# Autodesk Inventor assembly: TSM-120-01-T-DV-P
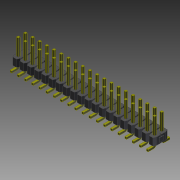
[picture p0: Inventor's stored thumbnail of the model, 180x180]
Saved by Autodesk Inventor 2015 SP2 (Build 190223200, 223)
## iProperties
Category: PARTsolutions
Company: SAMTEC
Created: 2015-08
Part Number: TSM-120-01-T-DV-P
Catalog Web Link: www.cadenas.de
Description: TSM Series-TSM Series - (2,54 mm) .100" Surface Mount Terminal .025" Square Post Header
Vendor: SAMTEC
Document SubType Name: Assembly
Designer: PARTuser1
Manufacturer: SAMTEC
Mass: 0.912016 g
Surface Area: 33.3654 cm^2
Volume: 0.912016 cm^3
Density: 1 g/cm^3
PSOL_IDENT_0: {$CADENAS_DATA\23d-libs\samtec\modelling\tsm\tsm_asmtab.prj},250 {VTYP=3D},{STYP=ASSTAB},{NB=TSM-120
PSOL_IDENT_1: -01-T-DV-P},{LINA=TSM-120-01-T-DV-P},{NN=TSM Series},{DATE=15.05.2015 12:28:13},{GEOMDATE=24.10.2014
PSOL_IDENT_2: 07:26:55},{VERSION=},{LINEID=10},{LINESUBID=-1},{WBVAR=POS,LS,ROW,PLOPT,LCOPT,AOPT,SLOPT,POLOPT,POP
PSOL_IDENT_3: T,TROPT,KOPT}  {NB=TSM-120-01-T-DV-P},{LINA=TSM-120-01-T-DV-P},{KT=DUMMY},{PN=TSM-120-01-T-DV-P},{SE
PSOL_IDENT_4: RIES=TSM},{POS=20},{POSPN=20},{LS=-01},{LSALG= '-01','-01','-02','-02','-03','-03','-04','-04' ,'-05'
PSOL_IDENT_5: ,'-05 (Non-standard option -  Please contact SAMTEC)' },{ROW=-DV},{ROWALG= '-SV','-SV - Single Verti
PSOL_IDENT_6: cal', '-SH','-SH - Single Horizontal', '-DV' ,'-DV - Double Vertical' ,'-DV-S' ,'-DV-S - Double Vert
PSOL_IDENT_7: ical Molded End Shrouds (Non-standard option -  Please contact SAMTEC)', '-DH', '-DH - Double Horizo
PSOL_IDENT_8: ntal' ,  '-MT','-MT - Mixed Technology','-EM','-EM - Edge Mount', '-TM','-TM - Triple Mixed Technolo
PSOL_IDENT_9: gy'  },{PLOPT=-T},{PLOPTALG= '-T','-T - Matte Tin on Entire Pin','-S','-S - 30micro\" Selective Gold
PSOL_IDENT_10: in Contact Area, Matte Tin on Tail','-G','-G - 10micro\" Selective Gold in Contact Area, 3micro\" S
PSOL_IDENT_11: elective Gold on Tail (Non-standard option -  Please contact SAMTEC)','-L','-L - 10micro\" Selective
PSOL_IDENT_12: Gold in Contact Area, Matte Tin on Tail','-TL','-TL - Tin/Lead (90/10) on Entire Pin (Non-standard
PSOL_IDENT_13: option -  Please contact SAMTEC)','-STL','-STL - 30micro\" Selective Gold in Contact Area, Tin/Lead
PSOL_IDENT_14: (90/10) on Tail (Non-standard option -  Please contact SAMTEC)','-F','-F - 3micro\" Selective Gold i
PSOL_IDENT_15: n Contact Area, Matte Tin on Tail (Non-standard option -  Please contact SAMTEC)','-H','-H - 30micro
PSOL_IDENT_16: \" Selective Gold in Contact Area, Matte Tin on Tail (Non-standard option -  Please contact SAMTEC)'
PSOL_IDENT_17: ,'-TM','-TM - Matte Tin on Entire Pin (Non-standard option -  Please contact SAMTEC)','-SM','-SM - 3
PSOL_IDENT_18: 0micro\" Selective Gold in Contact Area, Matte Tin on Tail (Non-standard option -  Please contact SA
PSOL_IDENT_19: MTEC)','-LM','-LM - 10micro\" Selective Gold in Contact Area, Matte Tin on Tail (Non-standard option
PSOL_IDENT_20: -  Please contact SAMTEC)','-FM','-FM - 3micro\" Selective Gold in Contact Area, Matte Tin on Tail
PSOL_IDENT_21: (Non-standard option -  Please contact SAMTEC)','-SS','-SS - 30micro\" Stripe Selective Gold in Cont
PSOL_IDENT_22: act Area, Matte Tin on Tail (Non-standard option -  Please contact SAMTEC)' },{LCOPT=},{LCOPTALG= ''
PSOL_IDENT_23: ,'Not Selected','-LC','-LC - Locking Clip' },{AOPT=},{AOPTALG= '','Not Selected','-A' , '-A - Alignm
PSOL_IDENT_24: ent Pin'  },{SLOPT=},{SLOPTALG= '','Not Available' },{POLOPT=},{POLOPTALG= '','Not Selected','001','
PSOL_IDENT_25: 001','002','002','003','003','004','004','005','005','006','006','007','007','008','008','009','009'
PSOL_IDENT_26: ,'010','010','011','011','012','012','013','013','014','014','015','015','016','016','017','017','01
PSOL_IDENT_27: 8','018','019','019','020','020','021','021','022','022','023','023','024','024','025','025','026','
PSOL_IDENT_28: 026','027','027','028','028','029','029','030','030','031','031','032','032','033','033','034','034'
PSOL_IDENT_29: ,'035','035','036','036','037','037','038','038','039','039','040','040' },{POLOPTMAX=480},{POLOPTMA
PSOL_IDENT_30: X2='001','001','002','002','003','003','004','004','005','005','006','006','007','007','008','008','
PSOL_IDENT_31: 009','009','010','010','011','011','012','012','013','013','014','014','015','015','016','016','017'
PSOL_IDENT_32: ,'017','018','018','019','019','020','020','021','021','022','022','023','023','024','024','025','02
PSOL_IDENT_33: 5','026','026','027','027','028','028','029','029','030','030','031','031','032','032','033','033','
PSOL_IDENT_34: 034','034','035','035','036','036','037','037','038','038','039','039','040','040'},{POLARIZE='001','
PSOL_IDENT_35: 001','002','002','003','003','004','004','005','005','006','006','007','007','008','008','009','009'
PSOL_IDENT_36: ,'010','010','011','011','012','012','013','013','014','014','015','015','016','016','017','017','01
PSOL_IDENT_37: 8','018','019','019','020','020','021','021','022','022','023','023','024','024','025','025','026','
PSOL_IDENT_38: 026','027','027','028','028','029','029','030','030','031','031','032','032','033','033','034','034'
PSOL_IDENT_39: ,'035','035','036','036','037','037','038','038','039','039','040','040','041','041','042','042','04
PSOL_IDENT_40: 3','043','044','044','045','045','046','046','047','047','048','048','049','049','050','050','051','
PSOL_IDENT_41: 051','052','052','053','053','054','054','055','055','056','056','057','057','058','058','059','059'
PSOL_IDENT_42: ,'060','060','061','061','062','062','063','063','064','064','065','065','066','066','067','067','06
PSOL_IDENT_43: 8','068','069','069','070','070','071','071','072','072','073','073','074','074','075','075','076','
PSOL_IDENT_44: 076','077','077','078','078','079','079','080','080','081','081','082','082','083','083','084','084'
PSOL_IDENT_45: ,'085','085','086','086','087','087','088','088','089','089','090','090','091','091','092','092','09
PSOL_IDENT_46: 3','093','094','094','095','095','096','096','097','097','098','098','099','099','100','100','101','
PSOL_IDENT_47: 101','102','102','103','103','104','104','105','105','106','106','107','107','108','108','109','109'
PSOL_IDENT_48: ,'110','110','111','111','112','112','113','113','114','114','115','115','116','116','117','117','11
PSOL_IDENT_49: 8','118','119','119','120','120','121','121','122','122','123','123','124','124','125','125','126','
PSOL_IDENT_50: 126','127','127','128','128','129','129','130','130','131','131','132','132','133','133','134','134'
PSOL_IDENT_51: ,'135','135','136','136','137','137','138','138','139','139','140','140','141','141','142','142','14
PSOL_IDENT_52: 3','143','144','144','145','145','146','146','147','147','148','148','149','149','150','150'},{POLOP
PSOL_IDENT_53: TPN=},{POPT=-P},{POPTALG= '','Not Selected','-P','-P - Pick & Place Pad' },{TROPT=},{TROPTALG= '','N
PSOL_IDENT_54: ot Selected','-TR','-TR - Tape & Reel' },{KOPT=},{KOPTALG= '','Not Available' },{PPATH=../tsm/parts/
PSOL_IDENT_55: tsm_asmtpl.prj}
NN: TSM Series
NT: TSM Series - (2,54 mm) .100" Surface Mount Terminal .025" Square Post Header
NB: TSM-120-01-T-DV-P
NBSYN: $PN.
LINA: TSM-120-01-T-DV-P
PN: TSM-120-01-T-DV-P
SERIES: TSM
POS: 20
LS: -01
ROW: -DV - Double Vertical
PLOPT: -T - Matte Tin on Entire Pin
LCOPT: Not Selected
AOPT: Not Selected
SLOPT: Not Available
POLOPT: Not Selected
POPT: -P - Pick & Place Pad
TROPT: Not Selected
KOPT: Not Available
SUPPLIER: SAMTEC
ARTICLENO: TSM-120-01-T-DV-P
BOMINFO: TSM-120-01-T-DV-P
CREATOR: CADENAS GmbH
Title: TSM-120-01-T-DV-P
Author: Cadenas PARTsolutions
Comments: TSM Series - (2,54 mm) .100" Surface Mount Terminal .025" Square Post Header
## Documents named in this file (4)
- D:\Tigers SVN\mechanik\2016\Inventor\Kaufteile\TSM-120-01-T-DV-P\TSM-120-01-T-DV-P.iam
- D:\Tigers SVN\mechanik\2016\Inventor\Kaufteile\TSM-120-01-T-DV-P\TSM-120-01-T-DV-P_body.ipt
- D:\Tigers SVN\mechanik\2016\Inventor\Kaufteile\TSM-120-01-T-DV-P\PPP-06-01-20--DV.ipt
- D:\Tigers SVN\mechanik\2016\Inventor\Kaufteile\TSM-120-01-T-DV-P\T-1S6-16(-01-20-DV).ipt
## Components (3 placed, 3 different names)
1. TSM-120-01-T-DV-P_body:1
2. PPP-06-01-20--DV:1
3. T-1S6-16(-01-20-DV):1
